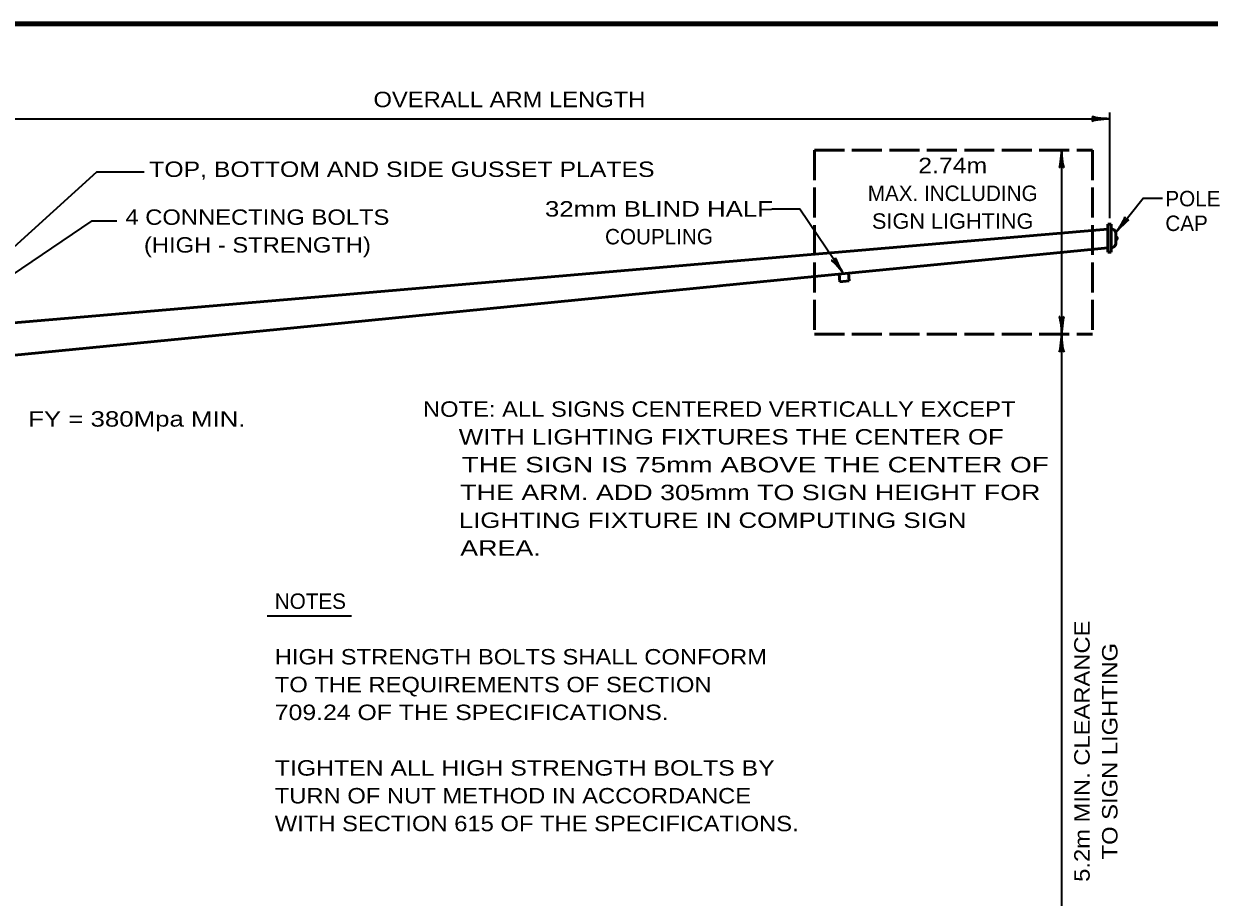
# Model space of a CAD drawing. Extents: x -39 to 816, y -16 to 528.
# Drawn here: x 157 to 387.3, y 352.1 to 521.9 of the extents above; entities that cross this region are included whole.
import ezdxf
from ezdxf.enums import TextEntityAlignment as Align

# ---------------------------------------------------------------- set-up
doc = ezdxf.new("R2010")
doc.units = 0
doc.header["$LTSCALE"] = 0.97
doc.linetypes.add('LONG_DASHED', pattern=[7.5, 6, -1.5])
doc.layers.add('1', color=7, linetype='Continuous', lineweight=35)

msp = doc.modelspace()

# ---------------------------------------------------------------- linework, layer by layer
at = {"layer": '1'}
for p, q in [((367.8854, 504.5729), (367.8854, 484.0785)), ((140.4734, 503.3729), (367.8854, 503.3729)), ((204.2818, 406.781), (220.6513, 406.781))]:
    msp.add_line(p, q, dxfattribs=at)
at = {"layer": '1', "linetype": 'LONG_DASHED', "lineweight": 53}
for p, q in [((310.5854, 497.2882), (310.5854, 461.5099)), ((310.5854, 497.2882), (364.5854, 497.2882)), ((364.5854, 497.2882), (364.5854, 461.5099)), ((310.5854, 461.5099), (364.5854, 461.5099))]:
    msp.add_line(p, q, dxfattribs=at)
at = {"layer": '1', "lineweight": 53}
for p, q in [((291.7214, 475.4385), (365.2558, 481.7457)), ((365.2574, 481.7265), (367.5614, 481.9425)), ((367.5854, 482.8785), (367.5854, 477.4305)), ((367.5854, 482.8785), (368.1854, 482.8785)), ((368.1854, 482.8785), (368.1854, 477.4305)), ((369.0974, 481.0545), (369.0974, 479.2545)), ((310.5854, 472.7112), (365.5928, 478.1088)), ((365.5934, 478.1025), (367.5614, 478.2945)), ((367.5854, 477.4305), (368.1854, 477.4305)), ((218.8094, 469.1985), (291.722, 475.431)), ((292.1534, 470.9025), (310.5854, 472.7111)), ((315.3624, 473.1799), (315.5089, 471.6871)), ((317.1537, 473.3557), (317.3002, 471.8629)), ((219.3374, 463.7505), (292.263, 470.9202)), ((315.5089, 471.6871), (317.3002, 471.8629)), ((141.0734, 462.5505), (218.8101, 469.1908)), ((141.0734, 456.0945), (219.3366, 463.7586))]:
    msp.add_line(p, q, dxfattribs=at)
at = {"layer": '1', "lineweight": 158}
msp.add_lwpolyline([(809.7034, 521.852), (18.0034, 521.752), (18.1034, -4.248)], dxfattribs=at)
at = {"layer": '1'}
for points in [[(358.5854, 497.2882), (358.5854, 461.5099), (358.5854, 292.9425)], [(136.721, 461.8196), (171.2007, 493.0593), (180.387, 493.0593)], [(369.0974, 481.3107), (374.412, 487.9562), (378.1633, 487.9562)], [(316.2005, 473.2622), (307.7429, 485.8471), (302.2615, 485.8471)], [(141.0734, 463.7985), (170.2637, 483.5716), (175.0457, 483.5716)]]:
    msp.add_lwpolyline(points, dxfattribs=at)
at = {"layer": '1', "lineweight": 53}
for centre, radius, start, end in [((368.236, 481.1047), 0.8581, 357.3286, 93.34376), ((368.236, 479.1978), 0.8581, 266.65624, 2.6714), ((369.0931, 480.1582), 0.3024, 270, 90)]:
    msp.add_arc(centre, radius, start, end, dxfattribs=at)
at = {"layer": '1', "lineweight": 40}
for centre, major_axis, ratio, start_param, end_param in [((366.576, 503.0413), (2.1428, 0.1874), 0.122415, 0.89635335, 3.14159265), ((366.5408, 503.6268), (2.1077, -0.2108), 0.07063, 3.14071475, 5.41810995), ((358.3315, 495.9436), (0.2108, 2.1077), 0.07063, 3.14071475, 5.41810995), ((358.3315, 495.9436), (0.2108, 2.1077), 0.07063, 3.14071475, 5.41810995), ((358.917, 495.9788), (-0.1874, 2.1428), 0.122415, 0.89635335, 3.14159265), ((358.917, 495.9788), (-0.1874, 2.1428), 0.122415, 0.89635335, 3.14159265), ((369.6563, 482.5404), (-1.192, -1.7905), 0.122415, 0.89635335, 3.14159265), ((370.1355, 482.2022), (-1.481, -1.5144), 0.07063, 3.14071475, 5.41810995), ((315.1949, 474.1641), (1.3508, -1.674), 0.122415, 0.89635335, 3.14159265), ((315.6612, 474.5198), (-1.0007, 1.867), 0.07063, 6.28230741, 8.55970261), ((358.2538, 462.8193), (0.1874, -2.1428), 0.122415, 0.89635335, 3.14159265), ((358.2538, 462.8193), (0.1874, -2.1428), 0.122415, 0.89635335, 3.14159265), ((358.8393, 462.8545), (-0.2108, -2.1077), 0.07063, 3.14071475, 5.41810995), ((358.8393, 462.8545), (-0.2108, -2.1077), 0.07063, 3.14071475, 5.41810995), ((358.3315, 460.1653), (0.2108, 2.1077), 0.07063, 3.14071475, 5.41810995), ((358.917, 460.2005), (-0.1874, 2.1428), 0.122415, 0.89635335, 3.14159265)]:
    msp.add_ellipse(centre, major_axis=major_axis, ratio=ratio, start_param=start_param, end_param=end_param, dxfattribs=at)

# ---------------------------------------------------------------- texts
at = {"layer": '1'}
for s, width, p in [('OVERALL ARM LENGTH', 1.15, (224.9067, 505.6341)), ('TOP, BOTTOM AND SIDE GUSSET PLATES', 1.2, (181.3379, 492.0754)), ('NOTE: ALL SIGNS CENTERED VERTICALLY EXCEPT', 1.15, (234.5146, 445.4741)), ('FY = 380Mpa MIN.', 1.25, (157.8281, 443.5574)), ('     WITH LIGHTING FIXTURES THE CENTER OF', 1.25, (234.5146, 440.0741)), ('     THE SIGN IS 75mm ABOVE THE CENTER OF', 1.35, (234.5146, 434.6741)), ('     THE ARM. ADD 305mm TO SIGN HEIGHT FOR', 1.3, (234.5146, 429.2741)), ('     LIGHTING FIXTURE IN COMPUTING SIGN', 1.25, (234.5146, 423.8741)), ('     AREA.', 1.3, (234.5146, 418.4741)), ('HIGH STRENGTH BOLTS SHALL CONFORM', 1.15, (205.7398, 397.3457)), ('TO THE REQUIREMENTS OF SECTION', 1.15, (205.7398, 391.9457)), ('709.24 OF THE SPECIFICATIONS.', 1.2, (205.7398, 386.5457)), ('TIGHTEN ALL HIGH STRENGTH BOLTS BY', 1.2, (205.7398, 375.7457)), ('TURN OF NUT METHOD IN ACCORDANCE', 1.15, (205.7398, 370.3457)), ('WITH SECTION 615 OF THE SPECIFICATIONS.', 1.15, (205.7398, 364.9457))]:
    msp.add_text(s, height=3, dxfattribs=dict(at, width=width)).set_placement(p)
for s, width, p in [('2.74m', 1.2, (337.4243, 492.8031)), ('32mm BLIND HALF', 1.25, (280.3644, 484.374)), ('4 CONNECTING BOLTS', 1.15, (202.3627, 482.7727)), ('SIGN LIGHTING', 1.05, (337.4244, 482.0031)), ('(HIGH - STRENGTH)', 1.15, (202.3628, 477.3727))]:
    msp.add_text(s, height=3, dxfattribs=dict(at, width=width)).set_placement(p, align=Align.CENTER)
for s, p in [('MAX. INCLUDING', (337.4243, 487.4031)), ('COUPLING', (280.3643, 478.974))]:
    msp.add_text(s, height=3, dxfattribs=at).set_placement(p, align=Align.CENTER)
for s, p in [('POLE', (378.7323, 486.3702)), ('CAP', (378.7323, 481.5702)), ('NOTES', (205.7398, 408.1457))]:
    msp.add_text(s, height=3, dxfattribs=at).set_placement(p)
at = {"layer": '1', "width": 1.15}
for s, p in [('5.2m MIN. CLEARANCE', (364.0333, 380.4947)), ('TO SIGN LIGHTING', (369.4333, 380.4947))]:
    msp.add_text(s, height=3, rotation=90, dxfattribs=at).set_placement(p, align=Align.CENTER)

doc.saveas('drawing.dxf')
